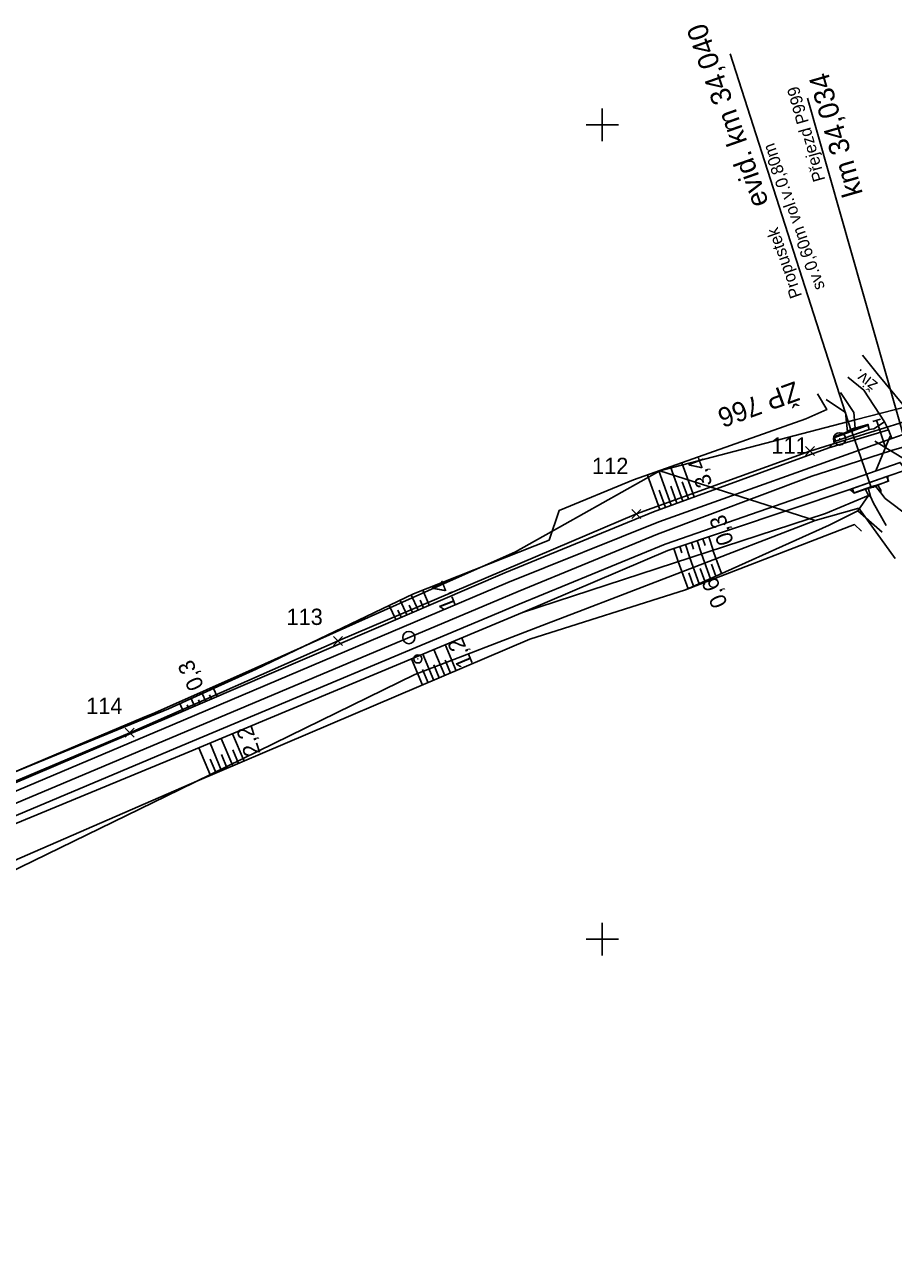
# Model space of a CAD drawing. Extents: x -805730 to -804640, y -1150889 to -1150366.
# Drawn here: x -804971 to -804864.2, y -1150637.9 to -1150487.7 of the extents above; entities that cross this region are included whole.
import ezdxf

# ---------------------------------------------------------------- set-up
doc = ezdxf.new("R2010")
doc.units = 0
for name, color, linetype in [('0381KM032-037P - Vrstva 1', 7, 'Continuous'), ('0381KM032-037P - Vrstva 17', 7, 'Continuous'), ('0381KM032-037P - Vrstva 19', 7, 'Continuous'), ('0381KM032-037P - Vrstva 4', 7, 'Continuous'), ('0381KM032-037P - Vrstva 48', 7, 'Continuous'), ('0381KM032-037P - Vrstva 49', 7, 'Continuous'), ('0381KM032-037P - Vrstva 51', 7, 'Continuous'), ('0381KM032-037P - Vrstva 55', 7, 'Continuous'), ('0381KM032-037P - Vrstva 7', 7, 'Continuous'), ('Default', 7, 'Continuous'), ('hran DP - hran DP', 7, 'Continuous'), ('krizky_1000 - Vrstva 1', 7, 'Continuous'), ('PSR_C2_2_Lomove_body_Vimperk - Vrstva 60', 7, 'Continuous'), ('PSR_C2_2_trasa_Vimperk - Kabelová trasa', 7, 'Continuous'), ('vyt_sit - ohrožené', 7, 'Continuous')]:
    doc.layers.add(name, color=color, linetype=linetype)

msp = doc.modelspace()

# ---------------------------------------------------------------- linework, layer by layer
at = {"layer": '0381KM032-037P - Vrstva 1'}
for points in [[(-804836.89, -1150533.13), (-804845.84, -1150535.01), (-804855.06, -1150537.3), (-804860.78, -1150538.93), (-804864.46, -1150539.98), (-804872.35, -1150542.54)], [(-804872.35, -1150542.54), (-804874.25, -1150543.16), (-804893.23, -1150550.28), (-804910.33, -1150557.31)], [(-804910.33, -1150557.31), (-804952.12, -1150574.92), (-804994.42, -1150592.71), (-805038.63, -1150611.27), (-805057.71, -1150619.3), (-805074.24, -1150626.27)]]:
    msp.add_lwpolyline(points, dxfattribs=at)
at = {"layer": '0381KM032-037P - Vrstva 17'}
for p, q in [((-804873.58, -1150533.02), (-804873.58, -1150533.02)), ((-804867.35, -1150536.9), (-804871.44, -1150538.39))]:
    msp.add_line(p, q, dxfattribs=at)
for points in [[(-804734.71, -1150510.96), (-804735.96, -1150513.84), (-804741.77, -1150514.83), (-804760.36, -1150517.2), (-804795.4, -1150521.06), (-804816.51, -1150523.78), (-804835.4, -1150526.88), (-804850, -1150530.66), (-804863.08, -1150534.36), (-804866.23, -1150530.55), (-804868.05, -1150528.28)], [(-804873.58, -1150533.02), (-804872.42, -1150534.97), (-804875, -1150536.1), (-804896.18, -1150543.61), (-804905.28, -1150547.35), (-804906.51, -1150551)], [(-804868.16, -1150549.89), (-804869.02, -1150549.09), (-804889.78, -1150557.12), (-804908.89, -1150563.18), (-804949.8, -1150580.61), (-804991.45, -1150598.69), (-805036.34, -1150617.58)], [(-804906.51, -1150551), (-804923.2, -1150557.6), (-804942.52, -1150566.83), (-804953.3, -1150571.71), (-804995.99, -1150589.23), (-805040.03, -1150605.68), (-805044.15, -1150607.13)]]:
    msp.add_lwpolyline(points, dxfattribs=at)
at = {"layer": '0381KM032-037P - Vrstva 19'}
for p, q in [((-804869.43, -1150537.57), (-804884.27, -1150491.28)), ((-804867.32, -1150536.83), (-804871.54, -1150538.31)), ((-804866.95, -1150544.56), (-804869.42, -1150537.44)), ((-804867.2, -1150537.4), (-804867.36, -1150536.8)), ((-804871.36, -1150538.86), (-804871.49, -1150538.28)), ((-804864.83, -1150543.77), (-804869.08, -1150545.22)), ((-804869.27, -1150544.65), (-804869.59, -1150544.8)), ((-804869.59, -1150544.8), (-804869.04, -1150545.2)), ((-804867.71, -1150544.71), (-804867.31, -1150545.53))]:
    msp.add_line(p, q, dxfattribs=at)
for points in [[(-804871.36, -1150538.86), (-804871.54, -1150538.31), (-804867.32, -1150536.83), (-804867.2, -1150537.4), (-804871.36, -1150538.86)], [(-804871.54, -1150538.31), (-804871.54, -1150538.31), (-804871.49, -1150538.28), (-804869.89, -1150537.71)], [(-804869.89, -1150537.71), (-804869.42, -1150537.44), (-804868.94, -1150537.26)], [(-804867.32, -1150536.83), (-804867.32, -1150536.83), (-804867.36, -1150536.8), (-804868.94, -1150537.26)], [(-804865.03, -1150543.19), (-804864.83, -1150543.77), (-804869.08, -1150545.22), (-804869.27, -1150544.65), (-804865.03, -1150543.19)], [(-804866.16, -1150544.27), (-804864.91, -1150543.76), (-804864.83, -1150543.77), (-804864.83, -1150543.77)], [(-804865.03, -1150543.19), (-804864.94, -1150543.15), (-804864.91, -1150543.76)], [(-804869.08, -1150545.22), (-804869.08, -1150545.22), (-804869.04, -1150545.2), (-804867.71, -1150544.71), (-804867.33, -1150544.58)], [(-804867.33, -1150544.58), (-804867.03, -1150545.63), (-804867.31, -1150545.53)]]:
    msp.add_lwpolyline(points, dxfattribs=at)
msp.add_lwpolyline([(-804866.45, -1150544.36), (-804866.16, -1150544.27), (-804865.77, -1150544.86), (-804865.78, -1150545.2)], close=True, dxfattribs=at)
for centre, major_axis, ratio in [((-804869.43, -1150537.43), (-0.407, -0.192), 0.02514), ((-804866.89, -1150544.48), (0.45, 0.118), 0.13222)]:
    msp.add_ellipse(centre, major_axis=major_axis, ratio=ratio, dxfattribs=at)
at = {"layer": '0381KM032-037P - Vrstva 4'}
for p, q in [((-804874.8, -1150496.75), (-804862.62, -1150539.46)), ((-804865.82, -1150536.14), (-804866.77, -1150536.45)), ((-804866.3, -1150536.29), (-804865.21, -1150539.62)), ((-804862.58, -1150541.24), (-804866.52, -1150538.84)), ((-804864.62, -1150538.22), (-804866.38, -1150542.48))]:
    msp.add_line(p, q, dxfattribs=at)
for points in [[(-804864.42, -1150538.53), (-804864.84, -1150537.45), (-804872.17, -1150539.66)], [(-804864.42, -1150538.53), (-804893.06, -1150548.77), (-804911.6, -1150556.2), (-804952.82, -1150573.68), (-804994.86, -1150591.44), (-805039.39, -1150610.13), (-805056.71, -1150617.44), (-805097.6, -1150634.39)], [(-804872.17, -1150539.66), (-804893.72, -1150547.52), (-804911.96, -1150555), (-804952.93, -1150572.63), (-804995.29, -1150590.69), (-805039.86, -1150609.18), (-805057.83, -1150616.69), (-805068.36, -1150621.07), (-805097.92, -1150633.57)], [(-804862.73, -1150542.41), (-804863.39, -1150541.46), (-804892.29, -1150551.48), (-804910.22, -1150558.86), (-804951.61, -1150576.23), (-804993.7, -1150593.96), (-805038.63, -1150612.92), (-805049.62, -1150617.53), (-805055.59, -1150619.94), (-805066.74, -1150624.75), (-805096.44, -1150637.01)], [(-804864.94, -1150543.15), (-804869.59, -1150544.8), (-804891.93, -1150552.26), (-804909.8, -1150559.87), (-804951.24, -1150577.2), (-804993.38, -1150594.6), (-805038.39, -1150613.8), (-805059.54, -1150622.79), (-805066.49, -1150625.57), (-805096.25, -1150637.87)], [(-804864.94, -1150543.15), (-804862.73, -1150542.41), (-804862.73, -1150542.41)]]:
    msp.add_lwpolyline(points, dxfattribs=at)
at = {"layer": '0381KM032-037P - Vrstva 48'}
for p, q in [((-804890.12, -1150546.21), (-804891.64, -1150542)), ((-804888.71, -1150545.7), (-804890.22, -1150541.5)), ((-804892.94, -1150547.24), (-804894.46, -1150543.01)), ((-804891.53, -1150546.73), (-804893.05, -1150542.5)), ((-804889.42, -1150545.95), (-804890.17, -1150543.85)), ((-804892.24, -1150546.98), (-804893, -1150544.87)), ((-804890.83, -1150546.47), (-804891.59, -1150544.36)), ((-804889.06, -1150551.3), (-804888.79, -1150552.11)), ((-804888.35, -1150551.06), (-804887.81, -1150552.69)), ((-804887.64, -1150550.83), (-804887.36, -1150551.65)), ((-804886.92, -1150550.59), (-804886.38, -1150552.23)), ((-804891.19, -1150552.02), (-804890.66, -1150553.62)), ((-804890.48, -1150551.78), (-804890.21, -1150552.58)), ((-804889.77, -1150551.54), (-804889.23, -1150553.16)), ((-804886.72, -1150555.74), (-804887.83, -1150552.7)), ((-804885.35, -1150555.12), (-804886.41, -1150552.24)), ((-804889.46, -1150556.98), (-804890.69, -1150553.63)), ((-804888.09, -1150556.36), (-804889.26, -1150553.17)), ((-804886.03, -1150555.43), (-804886.58, -1150553.95)), ((-804888.78, -1150556.67), (-804889.37, -1150555.03)), ((-804887.4, -1150556.05), (-804887.97, -1150554.49)), ((-804921.28, -1150559.01), (-804922.05, -1150557.14)), ((-804924.01, -1150560.18), (-804924.82, -1150558.38)), ((-804922.63, -1150559.59), (-804923.47, -1150557.73)), ((-804921.97, -1150559.3), (-804922.36, -1150558.36)), ((-804925.38, -1150560.77), (-804926.18, -1150559.02)), ((-804924.69, -1150560.48), (-804925.1, -1150559.59)), ((-804923.32, -1150559.88), (-804923.73, -1150558.97)), ((-804919.33, -1150567.63), (-804920.68, -1150564.42)), ((-804917.95, -1150567.04), (-804919.3, -1150563.84)), ((-804922.08, -1150568.8), (-804923.45, -1150565.58)), ((-804920.71, -1150568.22), (-804922.06, -1150565)), ((-804920.02, -1150567.92), (-804920.69, -1150566.31)), ((-804918.64, -1150567.33), (-804919.31, -1150565.73)), ((-804921.4, -1150568.51), (-804922.08, -1150566.9)), ((-804947.33, -1150570.22), (-804947.78, -1150569.21)), ((-804950.09, -1150571.4), (-804950.51, -1150570.45)), ((-804949.4, -1150571.11), (-804949.61, -1150570.62)), ((-804948.71, -1150570.81), (-804949.14, -1150569.83)), ((-804948.02, -1150570.52), (-804948.24, -1150570.02)), ((-804951.47, -1150572), (-804951.88, -1150571.07)), ((-804950.78, -1150571.7), (-804950.99, -1150571.23)), ((-804945.38, -1150578.73), (-804946.81, -1150575.35)), ((-804944, -1150578.14), (-804945.43, -1150574.77)), ((-804948.14, -1150579.91), (-804949.58, -1150576.51)), ((-804946.76, -1150579.32), (-804948.19, -1150575.93)), ((-804944.69, -1150578.44), (-804945.4, -1150576.75)), ((-804947.45, -1150579.61), (-804948.17, -1150577.92)), ((-804946.07, -1150579.03), (-804946.79, -1150577.33))]:
    msp.add_line(p, q, dxfattribs=at)
at = {"layer": '0381KM032-037P - Vrstva 49'}
for p, q in [((-804867.85, -1150532.57), (-804869.83, -1150530.99)), ((-804872.42, -1150534.97), (-804873.58, -1150533.02)), ((-804865.31, -1150536.46), (-804867.85, -1150532.57)), ((-804867.03, -1150545.63), (-804867.33, -1150544.58)), ((-804865.78, -1150545.2), (-804866.45, -1150544.36)), ((-804868.59, -1150547.42), (-804865.62, -1150550.04))]:
    msp.add_line(p, q, dxfattribs=at)
for points in [[(-804868.94, -1150537.26), (-804869.09, -1150535.33), (-804870.73, -1150532.86)], [(-804869.89, -1150537.71), (-804870.12, -1150535.33), (-804872.5, -1150533.72)], [(-804906.51, -1150551), (-804905.28, -1150547.35), (-804896.18, -1150543.61), (-804875, -1150536.1), (-804872.42, -1150534.97)], [(-804871.36, -1150538.86), (-804871.49, -1150538.28), (-804869.89, -1150537.71)], [(-804865.31, -1150536.46), (-804866.66, -1150537.33), (-804867.2, -1150537.4), (-804871.36, -1150538.86)], [(-804868.94, -1150537.26), (-804867.36, -1150536.8), (-804867.2, -1150537.4)], [(-804871.36, -1150538.86), (-804872.17, -1150539.66), (-804893.72, -1150547.52), (-804911.96, -1150555), (-804952.93, -1150572.63), (-804995.29, -1150590.69), (-805039.86, -1150609.18), (-805057.83, -1150616.69), (-805068.36, -1150621.07), (-805097.92, -1150633.57)], [(-804869.27, -1150544.65), (-804865.03, -1150543.19), (-804864.94, -1150543.15), (-804862.73, -1150542.41)], [(-804869.27, -1150544.65), (-804869.59, -1150544.8), (-804891.93, -1150552.26), (-804909.8, -1150559.87)], [(-804865.78, -1150545.2), (-804865.26, -1150545.89), (-804862.25, -1150548.13)], [(-804909.8, -1150559.87), (-804872.57, -1150547.72), (-804867.31, -1150545.53)], [(-804889.78, -1150557.12), (-804872.12, -1150549.16), (-804868.59, -1150547.42), (-804867.31, -1150545.53)], [(-804867.03, -1150545.63), (-804866.68, -1150546.48), (-804865.14, -1150549.2)], [(-804906.51, -1150551), (-804923.2, -1150557.6), (-804942.52, -1150566.83), (-804953.3, -1150571.71), (-804995.99, -1150589.23), (-805040.03, -1150605.68), (-805044.15, -1150607.13)], [(-804889.78, -1150557.12), (-804908.89, -1150563.18), (-804949.8, -1150580.61), (-804991.45, -1150598.69), (-805036.34, -1150617.58)], [(-804909.8, -1150559.87), (-804951.24, -1150577.2), (-804993.38, -1150594.6), (-805038.39, -1150613.8), (-805050.01, -1150619.25), (-805055.21, -1150621.51), (-805059.54, -1150622.79), (-805066.49, -1150625.57), (-805096.25, -1150637.87)]]:
    msp.add_lwpolyline(points, dxfattribs=at)
msp.add_ellipse((-804866.89, -1150544.48), major_axis=(0.45, 0.118), ratio=0.13222, start_param=2.866376, end_param=6.348957, dxfattribs=at)
at = {"layer": '0381KM032-037P - Vrstva 51'}
msp.add_line((-804867.85, -1150532.57), (-804869.83, -1150530.99), dxfattribs=at)
for points in [[(-804864.84, -1150537.45), (-804865.31, -1150536.46), (-804867.85, -1150532.57)], [(-804861.98, -1150536.58), (-804861.64, -1150537.54), (-804864.42, -1150538.53), (-804864.84, -1150537.45)]]:
    msp.add_lwpolyline(points, dxfattribs=at)
at = {"layer": '0381KM032-037P - Vrstva 55'}
msp.add_line((-804892.91, -1150542.49), (-804873.83, -1150548.59), dxfattribs=at)
at = {"layer": '0381KM032-037P - Vrstva 7'}
msp.add_line((-804922.71, -1150565.59), (-804922.61, -1150565.59), dxfattribs=at)
for centre, radius in [((-804923.76, -1150562.97), 0.75), ((-804922.66, -1150565.59), 0.5)]:
    msp.add_circle(centre, radius, dxfattribs=at)
at = {"layer": 'hran DP - hran DP'}
for p, q in [((-804868.93, -1150536.25), (-804855.75, -1150532.82)), ((-804892.91, -1150542.49), (-804868.93, -1150536.25)), ((-804904.62, -1150549.05), (-804892.91, -1150542.49)), ((-804868.47, -1150547.08), (-804873.83, -1150548.59)), ((-804864.02, -1150553.26), (-804868.47, -1150547.08)), ((-804910.68, -1150552.45), (-804904.62, -1150549.05)), ((-804873.83, -1150548.59), (-804889.79, -1150554.73)), ((-804919.88, -1150556.55), (-804910.68, -1150552.45)), ((-804889.79, -1150554.73), (-804898.28, -1150557.99)), ((-804930.31, -1150561.21), (-804919.88, -1150556.55)), ((-804898.28, -1150557.99), (-804902.34, -1150559.55)), ((-804902.34, -1150559.55), (-804906.85, -1150561.29)), ((-804942.65, -1150566.71), (-804930.31, -1150561.21)), ((-804906.85, -1150561.29), (-804923.02, -1150567.51)), ((-804954.99, -1150572.21), (-804942.65, -1150566.71)), ((-804923.02, -1150567.51), (-804951.89, -1150581.61)), ((-804956.48, -1150572.84), (-804954.99, -1150572.21)), ((-804968.41, -1150577.86), (-804956.48, -1150572.84)), ((-804981, -1150583.16), (-804968.41, -1150577.86)), ((-804951.89, -1150581.61), (-804973.16, -1150591.99))]:
    msp.add_line(p, q, dxfattribs=at)
at = {"layer": 'krizky_1000 - Vrstva 1'}
for points in [[(-804900, -1150498), (-804900, -1150502)], [(-804902, -1150500), (-804898, -1150500)], [(-804900, -1150598), (-804900, -1150602)], [(-804902, -1150600), (-804898, -1150600)]]:
    msp.add_lwpolyline(points, dxfattribs=at)
at = {"layer": 'PSR_C2_2_Lomove_body_Vimperk - Vrstva 60'}
for p, q in [((-804875.04, -1150540.62), (-804873.94, -1150539.52)), ((-804873.94, -1150540.62), (-804875.04, -1150539.52)), ((-804896.35, -1150548.34), (-804895.25, -1150547.24)), ((-804895.25, -1150548.34), (-804896.35, -1150547.24)), ((-804933.01, -1150563.93), (-804931.91, -1150562.83)), ((-804931.91, -1150563.93), (-804933.01, -1150562.83)), ((-804958.6, -1150575.21), (-804957.5, -1150574.11)), ((-804957.5, -1150575.21), (-804958.6, -1150574.11))]:
    msp.add_line(p, q, dxfattribs=at)
at = {"layer": 'PSR_C2_2_trasa_Vimperk - Kabelová trasa'}
msp.add_lwpolyline([(-804861.61, -1150536.05), (-804874.49, -1150540.07), (-804895.8, -1150547.79), (-804932.46, -1150563.38), (-804958.05, -1150574.66), (-804991.35, -1150588.71)], dxfattribs=at)
at = {"layer": 'vyt_sit - ohrožené'}
msp.add_line((-804870.89, -1150538.58), (-804870.79, -1150538.58), dxfattribs=at)
msp.add_circle((-804870.84, -1150538.58), 0.756, dxfattribs=at)

# ---------------------------------------------------------------- texts
at = {"layer": '0381KM032-037P - Vrstva 19'}
for s, height, rotation, p in [('evid. km 34,040', 2.5, 109.3587, (-804879.52, -1150509.62)), ('sv.0,60m vol.v.0,80m', 1.5, 109.4315, (-804872.62, -1150520)), ('Propustek', 1.5, 109.4315, (-804875.45, -1150521))]:
    msp.add_text(s, height=height, rotation=rotation, dxfattribs=at).set_placement(p)
at = {"layer": '0381KM032-037P - Vrstva 4'}
for s, height, rotation, p in [('km 34,034', 2.5, 106.0257, (-804867.97, -1150508.45)), ('Přejezd P999', 1.5, 105.8715, (-804872.6, -1150506.75))]:
    msp.add_text(s, height=height, rotation=rotation, dxfattribs=at).set_placement(p)
at = {"layer": '0381KM032-037P - Vrstva 48'}
for s, rotation, p in [('3,4', 110.0448, (-804886.43, -1150544.12)), ('0,3', 108.4626, (-804883.82, -1150551.25)), ('0,6', 113.0694, (-804884.56, -1150558.81)), ('1,4', 111.5655, (-804917.87, -1150559.18)), ('1,2', 112.6972, (-804915.82, -1150566.2)), ('0,3', 114.3346, (-804948.89, -1150568.92)), ('2,2', 107.6972, (-804941.96, -1150577.16))]:
    msp.add_text(s, height=2, rotation=rotation, dxfattribs=at).set_placement(p)
at = {"layer": '0381KM032-037P - Vrstva 51'}
msp.add_text('živ.', height=1.5, rotation=141.4462, dxfattribs=at).set_placement((-804866.05, -1150531.74))
at = {"layer": 'Default'}
for s, p in [('111', (-804879.23, -1150540.38)), ('112', (-804901.26, -1150542.89)), ('113', (-804938.8, -1150561.42)), ('114', (-804963.41, -1150572.35))]:
    msp.add_text(s, height=2, dxfattribs=at).set_placement(p)
at = {"layer": 'vyt_sit - ohrožené'}
msp.add_text('ŽP 766', height=2.4, rotation=200, dxfattribs=at).set_placement((-804876.31, -1150531.46))

doc.saveas('drawing.dxf')
